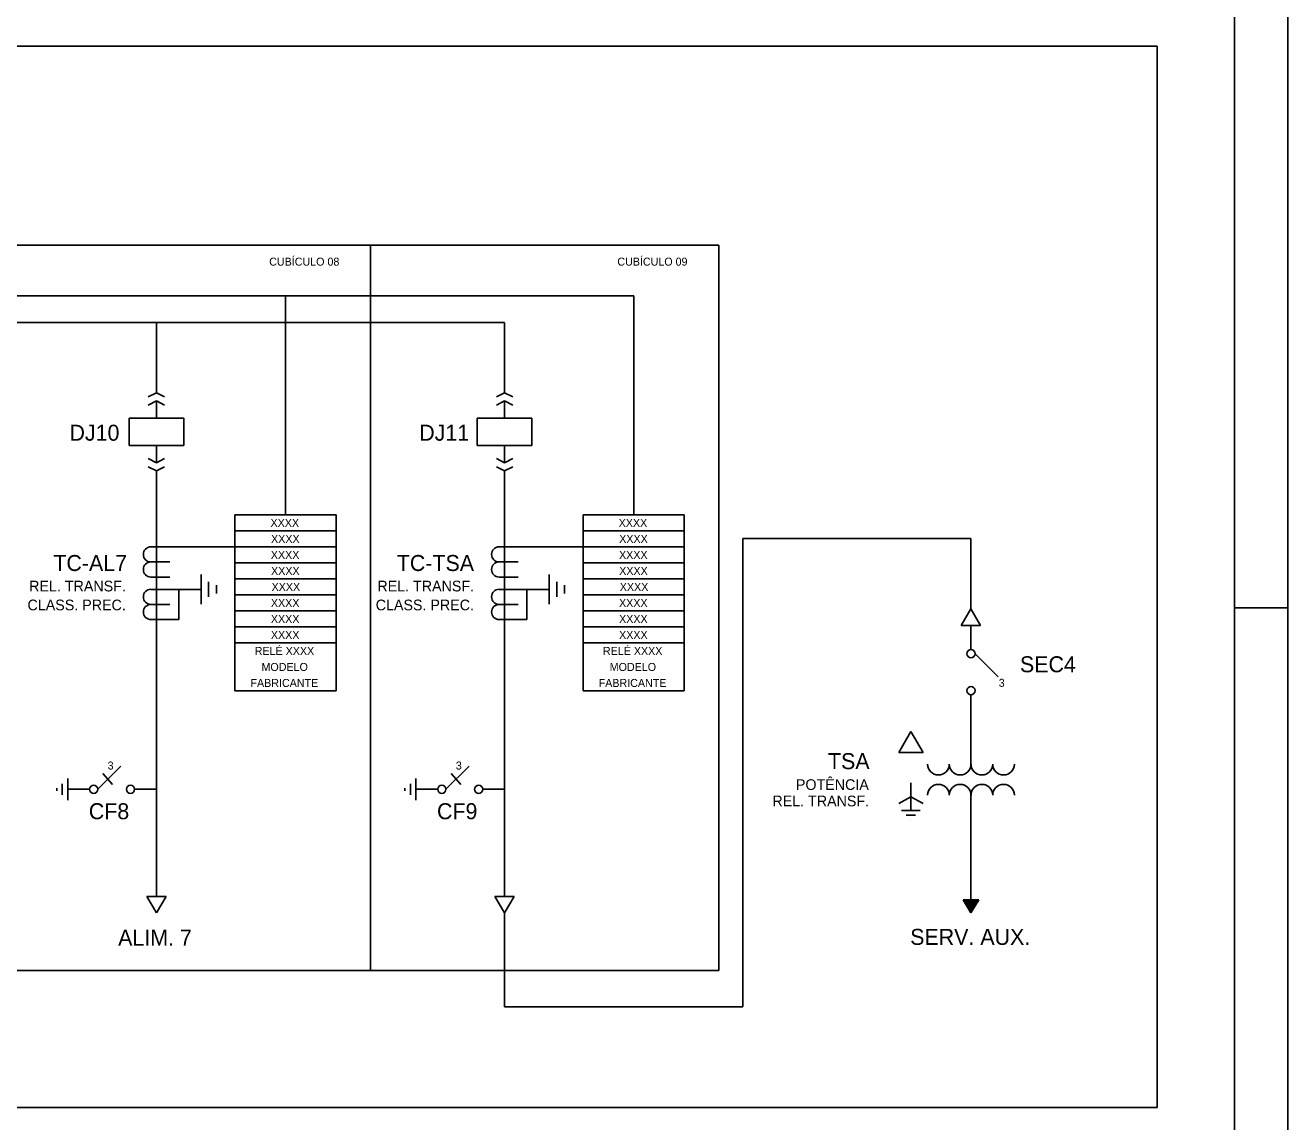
# Model space of a CAD drawing. Extents: x 563 to 1404, y 358 to 952.
# Drawn here: x 1166.9 to 1403.6, y 558.6 to 764.1 of the extents above; entities that cross this region are included whole.
import ezdxf

# ---------------------------------------------------------------- set-up
doc = ezdxf.new("R2010")
doc.units = 0
doc.layers.add('13', color=7, linetype='Continuous')
doc.layers.add('New Level (0)', color=7, linetype='Continuous')

msp = doc.modelspace()

# ---------------------------------------------------------------- linework, layer by layer
for p, q in [((1296.89, 722.95), (622.37, 722.95)), ((1231.61, 722.95), (1231.61, 586.96)), ((1231.61, 722.95), (1231.61, 586.96)), ((1296.89, 722.95), (1296.89, 586.96)), ((1296.89, 722.95), (1296.89, 586.96)), ((1280.96, 713.45), (705.72, 713.45)), ((1215.68, 672.38), (1215.68, 713.45)), ((1280.96, 672.38), (1280.96, 713.45)), ((1256.75, 708.46), (681.52, 708.46)), ((1191.48, 695.25), (1191.48, 708.46)), ((1191.48, 695.25), (1191.48, 708.46)), ((1256.75, 695.25), (1256.75, 708.46)), ((1256.75, 695.25), (1256.75, 708.46)), ((1191.48, 690.5), (1191.48, 693.73)), ((1191.48, 690.5), (1191.48, 693.73)), ((1256.75, 690.5), (1256.75, 693.73)), ((1256.75, 690.5), (1256.75, 693.73)), ((1186.35, 685.38), (1186.35, 690.5)), ((1186.35, 690.5), (1196.6, 690.5)), ((1196.6, 690.5), (1196.6, 685.38)), ((1251.63, 685.38), (1251.63, 690.5)), ((1251.63, 690.5), (1261.87, 690.5)), ((1261.87, 690.5), (1261.87, 685.38)), ((1196.6, 685.38), (1186.35, 685.38)), ((1191.48, 685.38), (1191.48, 682.16)), ((1261.87, 685.38), (1251.63, 685.38)), ((1256.75, 685.38), (1256.75, 682.16)), ((1191.48, 600.87), (1191.48, 680.63)), ((1256.75, 600.87), (1256.75, 680.63)), ((1225.17, 672.38), (1206.19, 672.38)), ((1206.19, 672.38), (1206.19, 639.38)), ((1225.17, 672.38), (1225.17, 639.38)), ((1290.45, 672.38), (1271.46, 672.38)), ((1271.46, 672.38), (1271.46, 639.38)), ((1290.45, 672.38), (1290.45, 639.38)), ((1225.17, 669.38), (1206.19, 669.38)), ((1290.45, 669.38), (1271.46, 669.38)), ((1301.4, 580.16), (1301.4, 667.97)), ((1301.4, 667.97), (1344.19, 667.97)), ((1344.19, 654.77), (1344.19, 667.97)), ((1190.45, 666.38), (1193.99, 666.38)), ((1206.19, 666.38), (1193.99, 666.38)), ((1225.17, 666.38), (1206.19, 666.38)), ((1255.73, 666.38), (1259.27, 666.38)), ((1271.46, 666.38), (1259.27, 666.38)), ((1290.45, 666.38), (1271.46, 666.38)), ((1190.45, 663.55), (1193.99, 663.55)), ((1225.17, 663.38), (1206.19, 663.38)), ((1255.73, 663.55), (1259.27, 663.55)), ((1290.45, 663.38), (1271.46, 663.38)), ((1190.45, 660.72), (1193.99, 660.72)), ((1199.85, 661.21), (1199.85, 655.63)), ((1225.17, 660.38), (1206.19, 660.38)), ((1255.73, 660.72), (1259.27, 660.72)), ((1265.13, 661.21), (1265.13, 655.63)), ((1290.45, 660.38), (1271.46, 660.38)), ((1190.45, 658.42), (1193.99, 658.42)), ((1191.48, 658.42), (1199.85, 658.42)), ((1201.25, 657.02), (1201.25, 659.82)), ((1202.73, 659.2), (1202.73, 657.64)), ((1255.73, 658.42), (1259.27, 658.42)), ((1256.75, 658.42), (1265.13, 658.42)), ((1266.53, 657.02), (1266.53, 659.82)), ((1268.01, 659.2), (1268.01, 657.64)), ((1225.17, 657.38), (1206.19, 657.38)), ((1290.45, 657.38), (1271.46, 657.38)), ((1190.45, 655.59), (1193.99, 655.59)), ((1225.17, 654.38), (1206.19, 654.38)), ((1225.17, 654.38), (1206.19, 654.38)), ((1255.73, 655.59), (1259.27, 655.59)), ((1290.45, 654.38), (1271.46, 654.38)), ((1290.45, 654.38), (1271.46, 654.38)), ((1344.19, 654.77), (1342.38, 651.67)), ((1346, 651.67), (1344.19, 654.77)), ((1190.45, 652.76), (1195.66, 652.76)), ((1225.17, 651.38), (1206.19, 651.38)), ((1255.73, 652.76), (1260.94, 652.76)), ((1290.45, 651.38), (1271.46, 651.38)), ((1342.38, 651.67), (1346, 651.67)), ((1342.38, 651.67), (1346, 651.67)), ((1344.19, 647.12), (1344.19, 651.67)), ((1225.17, 648.38), (1206.19, 648.38)), ((1290.45, 648.38), (1271.46, 648.38)), ((1349.3, 642.02), (1344.96, 646.36)), ((1225.17, 639.38), (1206.19, 639.38)), ((1290.45, 639.38), (1271.46, 639.38)), ((1344.19, 638.68), (1344.19, 625.66)), ((1330.68, 627.86), (1332.94, 631.79)), ((1330.68, 627.86), (1332.94, 631.79)), ((1330.68, 627.86), (1332.94, 631.79)), ((1330.68, 627.86), (1332.94, 631.79)), ((1330.68, 627.86), (1332.94, 631.79)), ((1332.94, 631.79), (1335.2, 627.86)), ((1332.94, 631.79), (1335.2, 627.86)), ((1332.94, 631.79), (1335.2, 627.86)), ((1332.94, 631.79), (1335.2, 627.86)), ((1332.94, 631.79), (1335.2, 627.86)), ((1335.2, 627.86), (1330.68, 627.86)), ((1335.2, 627.86), (1330.68, 627.86)), ((1335.2, 627.86), (1330.68, 627.86)), ((1335.2, 627.86), (1330.68, 627.86)), ((1335.2, 627.86), (1330.68, 627.86)), ((1184.81, 625.29), (1180.47, 620.95)), ((1250.09, 625.29), (1245.75, 620.95)), ((1174.84, 623), (1174.84, 618.91)), ((1181.46, 623.9), (1183.26, 621.88)), ((1240.12, 623), (1240.12, 618.91)), ((1246.74, 623.9), (1248.54, 621.88)), ((1172.8, 621.19), (1172.8, 620.66)), ((1173.82, 619.93), (1173.82, 621.98)), ((1178.94, 620.95), (1174.84, 620.95)), ((1191.48, 620.95), (1187.38, 620.95)), ((1238.08, 621.19), (1238.08, 620.66)), ((1239.09, 619.93), (1239.09, 621.98)), ((1244.21, 620.95), (1240.12, 620.95)), ((1256.75, 620.95), (1252.66, 620.95)), ((1332.93, 622.18), (1332.93, 616.95)), ((1332.93, 622.18), (1332.93, 616.95)), ((1332.93, 622.18), (1332.93, 616.95)), ((1332.93, 622.18), (1332.93, 616.95)), ((1332.93, 622.18), (1332.93, 616.95)), ((1332.93, 619.56), (1330.67, 618.26)), ((1332.93, 619.56), (1330.67, 618.26)), ((1332.93, 619.56), (1330.67, 618.26)), ((1332.93, 619.56), (1330.67, 618.26)), ((1332.93, 619.56), (1330.67, 618.26)), ((1332.93, 619.56), (1335.2, 618.26)), ((1332.93, 619.56), (1335.2, 618.26)), ((1335.2, 618.26), (1332.93, 619.56)), ((1332.93, 619.56), (1335.2, 618.26)), ((1335.2, 618.26), (1332.93, 619.56)), ((1332.93, 619.56), (1335.2, 618.26)), ((1335.2, 618.26), (1332.93, 619.56)), ((1332.93, 616.95), (1332.93, 619.56)), ((1332.93, 619.56), (1335.2, 618.26)), ((1335.2, 618.26), (1332.93, 619.56)), ((1344.19, 599.32), (1344.19, 619.85)), ((1331.19, 616.95), (1334.68, 616.95)), ((1332.93, 616.95), (1331.19, 616.95)), ((1331.19, 616.95), (1334.68, 616.95)), ((1332.93, 616.95), (1331.19, 616.95)), ((1331.19, 616.95), (1334.68, 616.95)), ((1332.93, 616.95), (1331.19, 616.95)), ((1331.19, 616.95), (1334.68, 616.95)), ((1332.93, 616.95), (1331.19, 616.95)), ((1333.81, 616.08), (1332.06, 616.08)), ((1333.81, 616.08), (1332.06, 616.08)), ((1333.81, 616.08), (1332.06, 616.08)), ((1333.81, 616.08), (1332.06, 616.08)), ((1333.81, 616.08), (1332.06, 616.08)), ((1332.93, 615.21), (1332.93, 615.21)), ((1332.93, 615.21), (1332.93, 615.21)), ((1332.93, 615.21), (1332.93, 615.21)), ((1332.93, 615.21), (1332.93, 615.21)), ((1332.93, 615.21), (1332.93, 615.21)), ((1193.29, 600.87), (1189.67, 600.87)), ((1189.67, 600.87), (1191.48, 597.77)), ((1193.29, 600.87), (1189.67, 600.87)), ((1191.48, 597.77), (1193.29, 600.87)), ((1258.56, 600.87), (1254.94, 600.87)), ((1254.94, 600.87), (1256.75, 597.77)), ((1258.56, 600.87), (1254.94, 600.87)), ((1256.75, 597.77), (1258.56, 600.87)), ((1345.64, 600.25), (1342.74, 600.25)), ((1342.74, 600.25), (1344.19, 597.77)), ((1342.93, 600.15), (1344.19, 597.98)), ((1345.46, 600.15), (1342.93, 600.15)), ((1345.28, 600.04), (1343.11, 600.04)), ((1343.11, 600.04), (1344.19, 598.18)), ((1345.1, 599.94), (1343.29, 599.94)), ((1343.29, 599.94), (1344.19, 598.39)), ((1343.47, 599.84), (1344.19, 598.6)), ((1344.92, 599.84), (1343.47, 599.84)), ((1343.65, 599.73), (1344.19, 598.8)), ((1344.74, 599.73), (1343.65, 599.73)), ((1344.55, 599.63), (1343.83, 599.63)), ((1343.83, 599.63), (1344.19, 599.01)), ((1344.37, 599.53), (1344.01, 599.53)), ((1344.01, 599.53), (1344.19, 599.22)), ((1344.19, 597.77), (1345.64, 600.25)), ((1344.19, 597.98), (1345.46, 600.15)), ((1344.19, 598.18), (1345.28, 600.04)), ((1344.19, 598.39), (1345.1, 599.94)), ((1344.19, 598.6), (1344.92, 599.84)), ((1344.19, 598.8), (1344.74, 599.73)), ((1344.19, 599.01), (1344.55, 599.63)), ((1344.19, 599.22), (1344.37, 599.53)), ((1256.75, 580.16), (1256.75, 597.77)), ((1296.89, 586.96), (622.37, 586.96)), ((1256.75, 580.16), (1301.4, 580.16))]:
    msp.add_line(p, q)
for centre in [(1344.19, 646.36), (1344.19, 639.45), (1179.71, 620.95), (1186.61, 620.95), (1244.98, 620.95), (1251.89, 620.95)]:
    msp.add_circle(centre, 0.768)
for centre, radius, start, end in [((1190.45, 664.97), 1.42, 90, 270), ((1255.73, 664.97), 1.42, 90, 270), ((1190.45, 662.14), 1.42, 90, 270), ((1255.73, 662.14), 1.42, 90, 270), ((1190.45, 657.01), 1.42, 90, 270), ((1255.73, 657.01), 1.42, 90, 270), ((1190.45, 654.18), 1.42, 90, 270), ((1255.73, 654.18), 1.42, 90, 270), ((1338.09, 625.66), 2.03, 180, 0), ((1342.16, 625.66), 2.03, 180, 0), ((1346.23, 625.66), 2.03, 180, 0), ((1350.29, 625.66), 2.03, 180, 0), ((1338.09, 619.85), 2.03, 0, 180), ((1342.16, 619.85), 2.03, 0, 180), ((1346.23, 619.85), 2.03, 0, 180), ((1350.29, 619.85), 2.03, 0, 180)]:
    msp.add_arc(centre, radius, start, end)
at = {"layer": '13'}
for p, q in [((1191.48, 695.25), (1189.95, 694.49)), ((1191.48, 693.73), (1189.95, 692.97)), ((1191.48, 695.25), (1193, 694.49)), ((1191.48, 693.73), (1193, 692.97)), ((1256.75, 695.25), (1255.23, 694.49)), ((1256.75, 693.73), (1255.23, 692.97)), ((1256.75, 695.25), (1258.28, 694.49)), ((1256.75, 693.73), (1258.28, 692.97)), ((1191.48, 682.16), (1189.95, 682.92)), ((1191.48, 682.16), (1193, 682.92)), ((1256.75, 682.16), (1255.23, 682.92)), ((1256.75, 682.16), (1258.28, 682.92)), ((1191.48, 680.63), (1189.95, 681.4)), ((1191.48, 680.63), (1193, 681.4)), ((1256.75, 680.63), (1255.23, 681.4)), ((1256.75, 680.63), (1258.28, 681.4))]:
    msp.add_line(p, q, dxfattribs=at)
at = {"layer": 'New Level (0)'}
for p, q in [((1403.58, 357.96), (1403.58, 951.96)), ((1403.58, 357.96), (1403.58, 951.96)), ((1393.58, 367.96), (1393.58, 941.96)), ((1393.58, 367.96), (1393.58, 941.96)), ((1195.66, 658.42), (1195.66, 652.76)), ((1260.94, 658.42), (1260.94, 652.76)), ((1393.58, 654.96), (1403.58, 654.96))]:
    msp.add_line(p, q, dxfattribs=at)
msp.add_lwpolyline([(592.61, 760.21), (1379.09, 760.21), (1379.09, 561.33), (592.61, 561.33)], close=True, dxfattribs=at)

# ---------------------------------------------------------------- texts
for s, height, p in [('CUBÍCULO 08', 1.5, (1212.62, 719.09)), ('CUBÍCULO 09', 1.5, (1277.89, 719.09)), ('DJ10', 3, (1175.18, 686.28)), ('DJ11', 3, (1240.75, 686.28)), ('XXXX', 1.5, (1212.87, 670.13)), ('XXXX', 1.5, (1278.14, 670.13)), ('XXXX', 1.5, (1212.97, 667.13)), ('XXXX', 1.5, (1278.24, 667.13)), ('XXXX', 1.5, (1212.93, 664.13)), ('XXXX', 1.5, (1278.21, 664.13)), ('TC-AL7', 3, (1172.15, 661.86)), ('TC-TSA', 3, (1236.54, 661.86)), ('XXXX', 1.5, (1212.97, 661.13)), ('XXXX', 1.5, (1278.24, 661.13)), ('REL. TRANSF.', 2, (1167.62, 658.04)), ('XXXX', 1.5, (1213.07, 658.13)), ('REL. TRANSF.', 2, (1232.9, 658.04)), ('XXXX', 1.5, (1278.35, 658.13)), ('CLASS. PREC.', 2, (1167.31, 654.5)), ('XXXX', 1.5, (1212.94, 655.13)), ('CLASS. PREC.', 2, (1232.59, 654.5)), ('XXXX', 1.5, (1278.21, 655.13)), ('XXXX', 1.5, (1212.94, 652.13)), ('XXXX', 1.5, (1278.22, 652.13)), ('XXXX', 1.5, (1212.94, 649.13)), ('XXXX', 1.5, (1278.22, 649.13)), ('RELÉ XXXX', 1.5, (1209.91, 646.13)), ('RELÉ XXXX', 1.5, (1275.19, 646.13)), ('MODELO', 1.5, (1211.18, 643.13)), ('MODELO', 1.5, (1276.46, 643.13)), ('SEC4', 3, (1353.37, 642.88)), ('FABRICANTE', 1.5, (1209.11, 640.13)), ('FABRICANTE', 1.5, (1274.39, 640.13)), ('3', 1.5, (1349.39, 640.16)), ('TSA', 3, (1317.38, 624.73)), ('3', 1.5, (1182.33, 624.65)), ('3', 1.5, (1247.61, 624.65)), ('POTÊNCIA', 2, (1311.37, 620.83)), ('CF8', 3, (1178.8, 615.34)), ('CF9', 3, (1244.08, 615.34)), ('REL. TRANSF.', 2, (1306.96, 617.76)), ('ALIM. 7', 3, (1184.3, 591.64)), ('SERV. AUX.', 3, (1332.79, 591.79))]:
    msp.add_text(s, height=height).set_placement(p)

doc.saveas('drawing.dxf')
